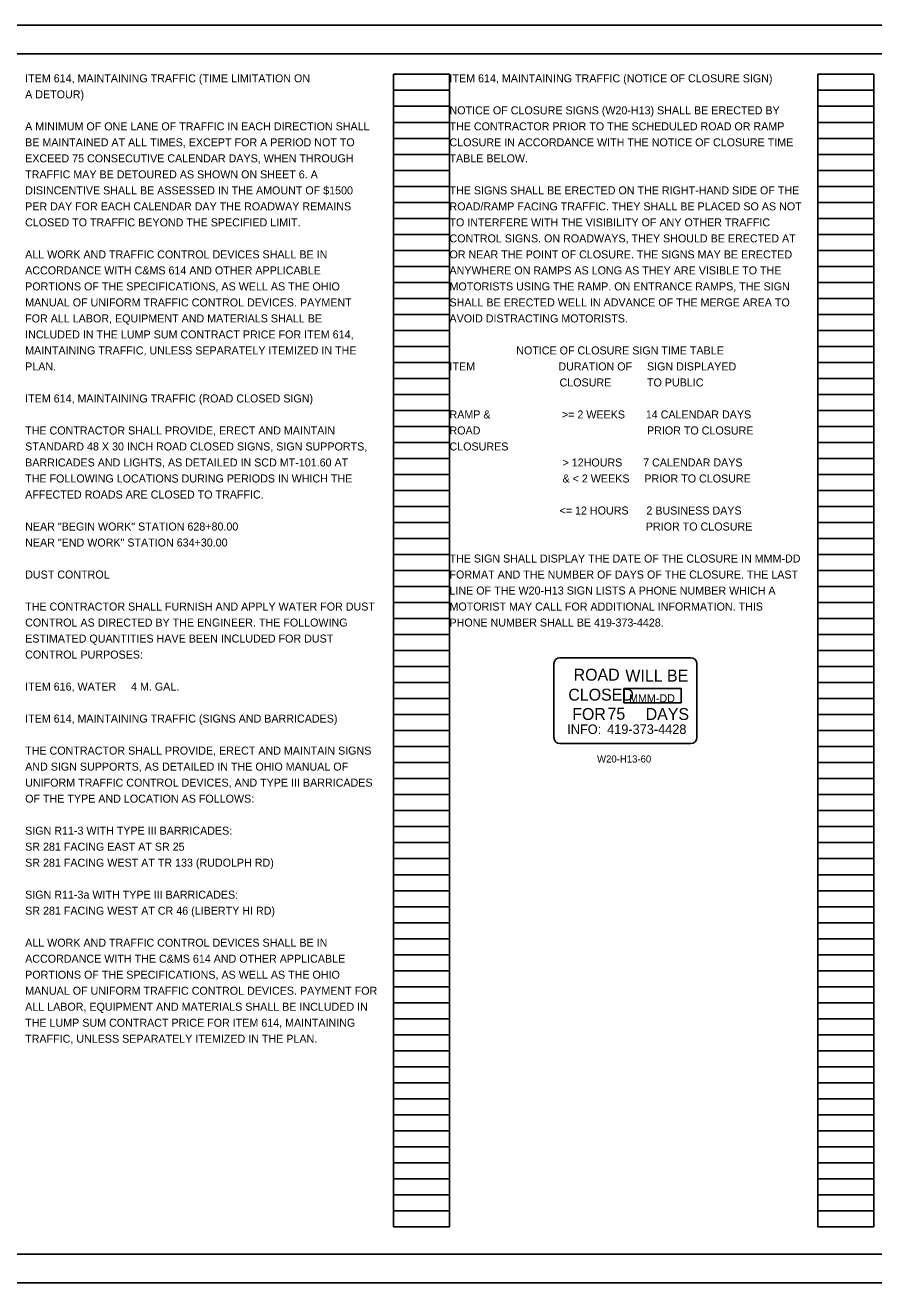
# Model space of a CAD drawing. Extents: x -7.7 to 42.4, y 0 to 36.3.
# Drawn here: x 2.4 to 17.24, y 0 to 22 of the extents above; entities that cross this region are included whole.
import ezdxf

# ---------------------------------------------------------------- set-up
doc = ezdxf.new("R2010")
doc.units = 0
for name, color, linetype in [('SH_Border', 7, 'Continuous'), ('SH_Cut_Line', 7, 'Continuous'), ('SH_Data', 7, 'Continuous'), ('SH_Text', 7, 'Continuous'), ('SN_P_Signs', 7, 'Continuous'), ('SN_P_Text', 7, 'Continuous')]:
    doc.layers.add(name, color=color, linetype=linetype)

msp = doc.modelspace()

# ---------------------------------------------------------------- linework, layer by layer
at = {"layer": 'SH_Border'}
msp.add_lwpolyline([(1.5, 21.5), (33.5, 21.5), (33.5, 0.5), (1.5, 0.5)], close=True, dxfattribs=at)
at = {"layer": 'SH_Cut_Line'}
msp.add_lwpolyline([(0, 0), (34, 0), (34, 22), (0, 22)], close=True, dxfattribs=at)
at = {"layer": 'SH_Data'}
for p, q in [((8.84, 0.98), (8.84, 21.14)), ((8.84, 21.14), (9.82, 21.14)), ((9.82, 0.98), (9.82, 21.14)), ((16.26, 0.98), (16.26, 21.14)), ((16.26, 21.14), (17.24, 21.14)), ((17.24, 0.98), (17.24, 21.14)), ((8.84, 20.86), (9.82, 20.86)), ((16.26, 20.86), (17.24, 20.86)), ((8.84, 20.58), (9.82, 20.58)), ((16.26, 20.58), (17.24, 20.58)), ((8.84, 20.3), (9.82, 20.3)), ((16.26, 20.3), (17.24, 20.3)), ((8.84, 20.02), (9.82, 20.02)), ((16.26, 20.02), (17.24, 20.02)), ((8.84, 19.74), (9.82, 19.74)), ((16.26, 19.74), (17.24, 19.74)), ((8.84, 19.46), (9.82, 19.46)), ((16.26, 19.46), (17.24, 19.46)), ((8.84, 19.18), (9.82, 19.18)), ((16.26, 19.18), (17.24, 19.18)), ((8.84, 18.9), (9.82, 18.9)), ((16.26, 18.9), (17.24, 18.9)), ((8.84, 18.62), (9.82, 18.62)), ((16.26, 18.62), (17.24, 18.62)), ((8.84, 18.34), (9.82, 18.34)), ((16.26, 18.34), (17.24, 18.34)), ((8.84, 18.06), (9.82, 18.06)), ((16.26, 18.06), (17.24, 18.06)), ((8.84, 17.78), (9.82, 17.78)), ((16.26, 17.78), (17.24, 17.78)), ((8.84, 17.5), (9.82, 17.5)), ((16.26, 17.5), (17.24, 17.5)), ((8.84, 17.22), (9.82, 17.22)), ((16.26, 17.22), (17.24, 17.22)), ((8.84, 16.94), (9.82, 16.94)), ((16.26, 16.94), (17.24, 16.94)), ((8.84, 16.66), (9.82, 16.66)), ((16.26, 16.66), (17.24, 16.66)), ((8.84, 16.38), (9.82, 16.38)), ((16.26, 16.38), (17.24, 16.38)), ((8.84, 16.1), (9.82, 16.1)), ((16.26, 16.1), (17.24, 16.1)), ((8.84, 15.82), (9.82, 15.82)), ((16.26, 15.82), (17.24, 15.82)), ((8.84, 15.54), (9.82, 15.54)), ((16.26, 15.54), (17.24, 15.54)), ((8.84, 15.26), (9.82, 15.26)), ((16.26, 15.26), (17.24, 15.26)), ((8.84, 14.98), (9.82, 14.98)), ((16.26, 14.98), (17.24, 14.98)), ((8.84, 14.7), (9.82, 14.7)), ((16.26, 14.7), (17.24, 14.7)), ((8.84, 14.42), (9.82, 14.42)), ((16.26, 14.42), (17.24, 14.42)), ((8.84, 14.14), (9.82, 14.14)), ((16.26, 14.14), (17.24, 14.14)), ((8.84, 13.86), (9.82, 13.86)), ((16.26, 13.86), (17.24, 13.86)), ((8.84, 13.58), (9.82, 13.58)), ((16.26, 13.58), (17.24, 13.58)), ((8.84, 13.3), (9.82, 13.3)), ((16.26, 13.3), (17.24, 13.3)), ((8.84, 13.02), (9.82, 13.02)), ((16.26, 13.02), (17.24, 13.02)), ((8.84, 12.74), (9.82, 12.74)), ((16.26, 12.74), (17.24, 12.74)), ((8.84, 12.46), (9.82, 12.46)), ((16.26, 12.46), (17.24, 12.46)), ((8.84, 12.18), (9.82, 12.18)), ((16.26, 12.18), (17.24, 12.18)), ((8.84, 11.9), (9.82, 11.9)), ((16.26, 11.9), (17.24, 11.9)), ((8.84, 11.62), (9.82, 11.62)), ((16.26, 11.62), (17.24, 11.62)), ((8.84, 11.34), (9.82, 11.34)), ((16.26, 11.34), (17.24, 11.34)), ((8.84, 11.06), (9.82, 11.06)), ((16.26, 11.06), (17.24, 11.06)), ((8.84, 10.78), (9.82, 10.78)), ((16.26, 10.78), (17.24, 10.78)), ((8.84, 10.5), (9.82, 10.5)), ((16.26, 10.5), (17.24, 10.5)), ((8.84, 10.22), (9.82, 10.22)), ((16.26, 10.22), (17.24, 10.22)), ((8.84, 9.94), (9.82, 9.94)), ((16.26, 9.94), (17.24, 9.94)), ((8.84, 9.66), (9.82, 9.66)), ((16.26, 9.66), (17.24, 9.66)), ((8.84, 9.38), (9.82, 9.38)), ((16.26, 9.38), (17.24, 9.38)), ((8.84, 9.1), (9.82, 9.1)), ((16.26, 9.1), (17.24, 9.1)), ((8.84, 8.82), (9.82, 8.82)), ((16.26, 8.82), (17.24, 8.82)), ((8.84, 8.54), (9.82, 8.54)), ((16.26, 8.54), (17.24, 8.54)), ((8.84, 8.26), (9.82, 8.26)), ((16.26, 8.26), (17.24, 8.26)), ((8.84, 7.98), (9.82, 7.98)), ((16.26, 7.98), (17.24, 7.98)), ((8.84, 7.7), (9.82, 7.7)), ((16.26, 7.7), (17.24, 7.7)), ((8.84, 7.42), (9.82, 7.42)), ((16.26, 7.42), (17.24, 7.42)), ((8.84, 7.14), (9.82, 7.14)), ((16.26, 7.14), (17.24, 7.14)), ((8.84, 6.86), (9.82, 6.86)), ((16.26, 6.86), (17.24, 6.86)), ((8.84, 6.58), (9.82, 6.58)), ((16.26, 6.58), (17.24, 6.58)), ((8.84, 6.3), (9.82, 6.3)), ((16.26, 6.3), (17.24, 6.3)), ((8.84, 6.02), (9.82, 6.02)), ((16.26, 6.02), (17.24, 6.02)), ((8.84, 5.74), (9.82, 5.74)), ((16.26, 5.74), (17.24, 5.74)), ((8.84, 5.46), (9.82, 5.46)), ((16.26, 5.46), (17.24, 5.46)), ((8.84, 5.18), (9.82, 5.18)), ((16.26, 5.18), (17.24, 5.18)), ((8.84, 4.9), (9.82, 4.9)), ((16.26, 4.9), (17.24, 4.9)), ((8.84, 4.62), (9.82, 4.62)), ((16.26, 4.62), (17.24, 4.62)), ((8.84, 4.34), (9.82, 4.34)), ((16.26, 4.34), (17.24, 4.34)), ((8.84, 4.06), (9.82, 4.06)), ((16.26, 4.06), (17.24, 4.06)), ((8.84, 3.78), (9.82, 3.78)), ((16.26, 3.78), (17.24, 3.78)), ((8.84, 3.5), (9.82, 3.5)), ((16.26, 3.5), (17.24, 3.5)), ((8.84, 3.22), (9.82, 3.22)), ((16.26, 3.22), (17.24, 3.22)), ((8.84, 2.94), (9.82, 2.94)), ((16.26, 2.94), (17.24, 2.94)), ((8.84, 2.66), (9.82, 2.66)), ((16.26, 2.66), (17.24, 2.66)), ((8.84, 2.38), (9.82, 2.38)), ((16.26, 2.38), (17.24, 2.38)), ((8.84, 2.1), (9.82, 2.1)), ((16.26, 2.1), (17.24, 2.1)), ((8.84, 1.82), (9.82, 1.82)), ((16.26, 1.82), (17.24, 1.82)), ((8.84, 1.54), (9.82, 1.54)), ((16.26, 1.54), (17.24, 1.54)), ((8.84, 1.26), (9.82, 1.26)), ((16.26, 1.26), (17.24, 1.26)), ((8.84, 0.98), (9.82, 0.98)), ((16.26, 0.98), (17.24, 0.98))]:
    msp.add_line(p, q, dxfattribs=at)
at = {"layer": 'SH_Text'}
msp.add_lwpolyline([(12.871, 10.398), (13.871, 10.398), (13.871, 10.148), (12.871, 10.148)], close=True, dxfattribs=at)
at = {"layer": 'SN_P_Signs'}
for p, q in [((11.646, 10.83), (11.646, 9.538)), ((14.042, 10.934), (11.75, 10.934)), ((14.146, 9.538), (14.146, 10.83)), ((11.75, 9.434), (14.042, 9.434))]:
    msp.add_line(p, q, dxfattribs=at)
for centre, start, end in [((11.75, 10.83), 90, 180), ((14.042, 10.83), 0, 90), ((11.75, 9.538), 180, 270), ((14.042, 9.538), 270, 360)]:
    msp.add_arc(centre, 0.104, start, end, dxfattribs=at)

# ---------------------------------------------------------------- texts
at = {"layer": 'SH_Text'}
for s, p in [('ITEM 614, MAINTAINING TRAFFIC (TIME LIMITATION ON', (2.4, 21)), ('ITEM 614, MAINTAINING TRAFFIC (NOTICE OF CLOSURE SIGN)', (9.82, 21)), ('A DETOUR)', (2.4, 20.72)), ('NOTICE OF CLOSURE SIGNS (W20-H13) SHALL BE ERECTED BY', (9.82, 20.44)), ('A MINIMUM OF ONE LANE OF TRAFFIC IN EACH DIRECTION SHALL', (2.4, 20.16)), ('THE CONTRACTOR PRIOR TO THE SCHEDULED ROAD OR RAMP', (9.82, 20.16)), ('BE MAINTAINED AT ALL TIMES, EXCEPT FOR A PERIOD NOT TO', (2.4, 19.88)), ('CLOSURE IN ACCORDANCE WITH THE NOTICE OF CLOSURE TIME', (9.82, 19.88)), ('EXCEED 75 CONSECUTIVE CALENDAR DAYS, WHEN THROUGH', (2.4, 19.6)), ('TABLE BELOW.', (9.82, 19.6)), ('TRAFFIC MAY BE DETOURED AS SHOWN ON SHEET 6. A', (2.4, 19.32)), ('DISINCENTIVE SHALL BE ASSESSED IN THE AMOUNT OF $1500', (2.4, 19.04)), ('THE SIGNS SHALL BE ERECTED ON THE RIGHT-HAND SIDE OF THE', (9.82, 19.04)), ('PER DAY FOR EACH CALENDAR DAY THE ROADWAY REMAINS', (2.4, 18.76)), ('ROAD/RAMP FACING TRAFFIC. THEY SHALL BE PLACED SO AS NOT', (9.82, 18.76)), ('CLOSED TO TRAFFIC BEYOND THE SPECIFIED LIMIT.', (2.4, 18.48)), ('TO INTERFERE WITH THE VISIBILITY OF ANY OTHER TRAFFIC', (9.82, 18.48)), ('CONTROL SIGNS. ON ROADWAYS, THEY SHOULD BE ERECTED AT', (9.82, 18.2)), ('ALL WORK AND TRAFFIC CONTROL DEVICES SHALL BE IN', (2.4, 17.92)), ('OR NEAR THE POINT OF CLOSURE. THE SIGNS MAY BE ERECTED', (9.82, 17.92)), ('ACCORDANCE WITH C&MS 614 AND OTHER APPLICABLE', (2.4, 17.64)), ('ANYWHERE ON RAMPS AS LONG AS THEY ARE VISIBLE TO THE', (9.82, 17.64)), ('PORTIONS OF THE SPECIFICATIONS, AS WELL AS THE OHIO', (2.4, 17.36)), ('MOTORISTS USING THE RAMP. ON ENTRANCE RAMPS, THE SIGN', (9.82, 17.36)), ('MANUAL OF UNIFORM TRAFFIC CONTROL DEVICES. PAYMENT', (2.4, 17.08)), ('SHALL BE ERECTED WELL IN ADVANCE OF THE MERGE AREA TO', (9.82, 17.08)), ('FOR ALL LABOR, EQUIPMENT AND MATERIALS SHALL BE', (2.4, 16.8)), ('AVOID DISTRACTING MOTORISTS.', (9.82, 16.8)), ('INCLUDED IN THE LUMP SUM CONTRACT PRICE FOR ITEM 614,', (2.4, 16.52)), ('MAINTAINING TRAFFIC, UNLESS SEPARATELY ITEMIZED IN THE', (2.4, 16.24)), ('NOTICE OF CLOSURE SIGN TIME TABLE', (10.987, 16.24)), ('PLAN.', (2.4, 15.96)), ('ITEM                            DURATION OF     SIGN DISPLAYED', (9.82, 15.96)), ('                                     CLOSURE            TO PUBLIC', (9.82, 15.68)), ('ITEM 614, MAINTAINING TRAFFIC (ROAD CLOSED SIGN)', (2.4, 15.4)), ('RAMP &                        >= 2 WEEKS       14 CALENDAR DAYS', (9.82, 15.12)), ('THE CONTRACTOR SHALL PROVIDE, ERECT AND MAINTAIN', (2.4, 14.84)), ('ROAD                                                        PRIOR TO CLOSURE', (9.82, 14.84)), ('STANDARD 48 X 30 INCH ROAD CLOSED SIGNS, SIGN SUPPORTS,', (2.4, 14.56)), ('CLOSURES', (9.82, 14.56)), ('BARRICADES AND LIGHTS, AS DETAILED IN SCD MT-101.60 AT', (2.4, 14.28)), ('                                      > 12HOURS       7 CALENDAR DAYS', (9.82, 14.28)), ('THE FOLLOWING LOCATIONS DURING PERIODS IN WHICH THE', (2.4, 14)), ('                                      & < 2 WEEKS     PRIOR TO CLOSURE', (9.82, 14)), ('AFFECTED ROADS ARE CLOSED TO TRAFFIC.', (2.4, 13.72)), ('                                     <= 12 HOURS      2 BUSINESS DAYS', (9.82, 13.44)), ('NEAR "BEGIN WORK" STATION 628+80.00', (2.4, 13.16)), ('                                                                  PRIOR TO CLOSURE', (9.82, 13.16)), ('NEAR "END WORK" STATION 634+30.00', (2.4, 12.88)), ('THE SIGN SHALL DISPLAY THE DATE OF THE CLOSURE IN MMM-DD', (9.82, 12.6)), ('DUST CONTROL', (2.4, 12.32)), ('FORMAT AND THE NUMBER OF DAYS OF THE CLOSURE. THE LAST', (9.82, 12.32)), ('LINE OF THE W20-H13 SIGN LISTS A PHONE NUMBER WHICH A', (9.82, 12.04)), ('THE CONTRACTOR SHALL FURNISH AND APPLY WATER FOR DUST', (2.4, 11.76)), ('MOTORIST MAY CALL FOR ADDITIONAL INFORMATION. THIS', (9.82, 11.76)), ('CONTROL AS DIRECTED BY THE ENGINEER. THE FOLLOWING', (2.4, 11.48)), ('PHONE NUMBER SHALL BE 419-373-4428.', (9.82, 11.48)), ('ESTIMATED QUANTITIES HAVE BEEN INCLUDED FOR DUST', (2.4, 11.2)), ('CONTROL PURPOSES:', (2.4, 10.92)), ('ITEM 616, WATER     4 M. GAL.', (2.4, 10.36)), ('MMM-DD', (12.961, 10.155)), ('ITEM 614, MAINTAINING TRAFFIC (SIGNS AND BARRICADES)', (2.4, 9.8)), ('THE CONTRACTOR SHALL PROVIDE, ERECT AND MAINTAIN SIGNS', (2.4, 9.24)), ('AND SIGN SUPPORTS, AS DETAILED IN THE OHIO MANUAL OF', (2.4, 8.96)), ('UNIFORM TRAFFIC CONTROL DEVICES, AND TYPE III BARRICADES', (2.4, 8.68)), ('OF THE TYPE AND LOCATION AS FOLLOWS:', (2.4, 8.4)), ('SIGN R11-3 WITH TYPE III BARRICADES:', (2.4, 7.84)), ('SR 281 FACING EAST AT SR 25', (2.4, 7.56)), ('SR 281 FACING WEST AT TR 133 (RUDOLPH RD)', (2.4, 7.28)), ('SIGN R11-3a WITH TYPE III BARRICADES:', (2.4, 6.72)), ('SR 281 FACING WEST AT CR 46 (LIBERTY HI RD)', (2.4, 6.44)), ('ALL WORK AND TRAFFIC CONTROL DEVICES SHALL BE IN', (2.4, 5.88)), ('ACCORDANCE WITH THE C&MS 614 AND OTHER APPLICABLE', (2.4, 5.6)), ('PORTIONS OF THE SPECIFICATIONS, AS WELL AS THE OHIO', (2.4, 5.32)), ('MANUAL OF UNIFORM TRAFFIC CONTROL DEVICES. PAYMENT FOR', (2.4, 5.04)), ('ALL LABOR, EQUIPMENT AND MATERIALS SHALL BE INCLUDED IN', (2.4, 4.76)), ('THE LUMP SUM CONTRACT PRICE FOR ITEM 614, MAINTAINING', (2.4, 4.48)), ('TRAFFIC, UNLESS SEPARATELY ITEMIZED IN THE PLAN.', (2.4, 4.2))]:
    msp.add_text(s, height=0.14, dxfattribs=at).set_placement(p)
at = {"layer": 'SN_P_Signs'}
for s, height, p in [('ROAD', 0.2083, (11.991, 10.534)), ('WILL BE', 0.2083, (12.896, 10.518)), ('CLOSED', 0.2083, (11.898, 10.185)), ('FOR         DAYS', 0.20833, (11.966, 9.846)), ('75', 0.2083, (12.583, 9.851)), ('INFO:', 0.1666, (11.879, 9.601)), ('419-373-4428', 0.16658, (12.576, 9.601))]:
    msp.add_text(s, height=height, dxfattribs=at).set_placement(p)
at = {"layer": 'SN_P_Text'}
msp.add_text('W20-H13-60', height=0.125, dxfattribs=at).set_placement((12.4, 9.101))

doc.saveas('drawing.dxf')
